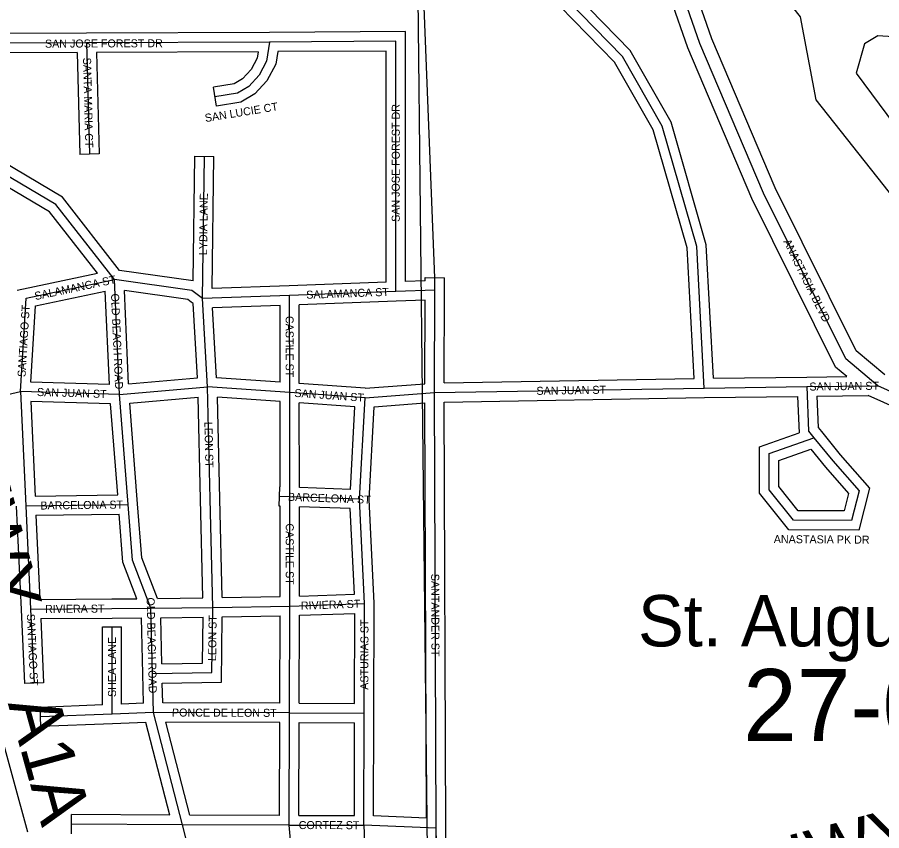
# Model space of a CAD drawing. Extents: x 418523 to 616617, y 1878279 to 2196743.
# Drawn here: x 566933 to 569632, y 2010108 to 2012645 of the extents above; entities that cross this region are included whole.
import ezdxf

# ---------------------------------------------------------------- set-up
doc = ezdxf.new("R2010")
doc.units = 0
for name, color, linetype in [('Level 1', 7, 'Continuous'), ('Level 2', 7, 'Continuous'), ('Level 22', 7, 'Continuous'), ('Level 23', 7, 'Continuous'), ('Level 28', 7, 'Continuous'), ('Level 31', 7, 'Continuous'), ('Level 32', 7, 'Continuous'), ('Level 34', 7, 'Continuous'), ('Level 44', 7, 'Continuous'), ('Level 5', 7, 'Continuous'), ('Level 8', 7, 'Continuous')]:
    doc.layers.add(name, color=color, linetype=linetype)

msp = doc.modelspace()

# ---------------------------------------------------------------- linework, layer by layer
at = {"layer": 'Level 1'}
msp.add_line((568168.027, 2014072.298), (568225.789, 2008858.623), dxfattribs=at)
at = {"layer": 'Level 22'}
for points in [[(569619.639, 2011495.826), (569519.67, 2011579.341), (569262.559, 2012096.71), (569063.974, 2012564.119), (568906.562, 2013014.704), (568898.539, 2013106.366), (568840.396, 2013181.781), (568832.354, 2013265.078)], [(571506.093, 2009348.016), (571532.95, 2009998.175), (571459.084, 2010407.097), (571417.473, 2010507.2), (571093.355, 2010849.789), (570477.21, 2011151.608), (569919.184, 2011361.657), (569619.639, 2011495.826)]]:
    msp.add_lwpolyline(points, dxfattribs=at)
at = {"layer": 'Level 23'}
msp.add_line((566965.801, 2010103.183), (566763.775, 2010837.889), dxfattribs=at)
for points in [[(569641.039, 2011530.071), (569551.756, 2011604.658), (569298.909, 2012113.446), (569101.304, 2012578.551), (568945.974, 2013023.175), (568937.365, 2013121.516), (568879.105, 2013197.086), (568871.6, 2013274.826)], [(569522.769, 2011524.63), (569487.584, 2011554.023), (569226.208, 2012079.973), (569026.644, 2012549.686), (568867.149, 2013006.234), (568859.711, 2013091.215), (568801.688, 2013166.477), (568793.637, 2013249.865)], [(571468.544, 2009408.178), (571492.801, 2009995.411), (571420.488, 2010395.734), (571383.359, 2010485.053), (571069.266, 2010817.047), (570461.33, 2011114.844), (569903.948, 2011324.651), (569589.599, 2011465.451)]]:
    msp.add_lwpolyline(points, dxfattribs=at)
at = {"layer": 'Level 31'}
for p, q in [((567149.488, 2012565.451), (566868.651, 2012564.315)), ((567720.038, 2012568.068), (567149.488, 2012565.451)), ((567149.488, 2012565.451), (567158.155, 2012218.498)), ((567511.125, 2011768.159), (567516.95, 2012211.446)), ((566960.859, 2011769.496), (567236.134, 2011827.376)), ((567251.748, 2011468.769), (567236.134, 2011827.376)), ((568236.428, 2011794.412), (568236.52, 2011832.96)), ((568236.428, 2011794.412), (568114.381, 2011789.614)), ((568235.662, 2011474.395), (568236.428, 2011794.412)), ((566943.35, 2011477.883), (566960.859, 2011769.496)), ((567783.114, 2011777.684), (567511.125, 2011768.159)), ((567526.943, 2011492.831), (567511.125, 2011768.159)), ((568114.381, 2011789.614), (567783.114, 2011777.684)), ((567783.334, 2011474.756), (567783.114, 2011777.684)), ((566618.267, 2011403.763), (566943.35, 2011477.883)), ((567251.748, 2011468.769), (566943.35, 2011477.883)), ((566943.35, 2011477.883), (566959.918, 2011121.456)), ((567251.748, 2011468.769), (567526.943, 2011492.831)), ((567783.334, 2011474.756), (567526.943, 2011492.831)), ((567535.289, 2011142.606), (567526.943, 2011492.831)), ((568018.809, 2011458.187), (567783.334, 2011474.756)), ((567783.502, 2011149.281), (567783.334, 2011474.756)), ((568018.809, 2011458.187), (568235.662, 2011474.395)), ((568235.662, 2011474.395), (569077.589, 2011488.747)), ((568240.331, 2010115.39), (568235.662, 2011474.395)), ((569077.589, 2011488.747), (569397.747, 2011493.079)), ((569397.747, 2011493.079), (569619.639, 2011495.826)), ((567278.81, 2011125.409), (567251.748, 2011468.769)), ((568001.249, 2011141.482), (568018.809, 2011458.187)), ((569280.288, 2011284.254), (569420.193, 2011333.743)), ((567783.502, 2011149.281), (567751.173, 2011150.45)), ((568001.249, 2011141.482), (567783.502, 2011149.281)), ((567783.633, 2010808.531), (567783.502, 2011149.281)), ((566959.918, 2011121.456), (567278.81, 2011125.409)), ((566959.918, 2011121.456), (566974.668, 2010799.22)), ((567543.349, 2010804.385), (567535.289, 2011142.606)), ((568016.952, 2010816.333), (568001.249, 2011141.482)), ((566974.668, 2010799.22), (567228.575, 2010800.783)), ((566974.668, 2010799.22), (566985.199, 2010567.907)), ((567228.575, 2010800.783), (567349.982, 2010801.58)), ((567349.982, 2010801.58), (567543.349, 2010804.385)), ((567354.877, 2010597.556), (567349.982, 2010801.58)), ((567543.349, 2010804.385), (567783.633, 2010808.531)), ((567782.829, 2010475.059), (567783.633, 2010808.531)), ((567783.633, 2010808.531), (568016.952, 2010816.333)), ((568016.131, 2010474.496), (568016.952, 2010816.333)), ((567228.728, 2010471.308), (567228.753, 2010743.326)), ((567357.754, 2010476.451), (567354.877, 2010597.556)), ((567357.754, 2010476.451), (567228.728, 2010471.308)), ((567782.829, 2010475.059), (567357.754, 2010476.451)), ((567448.516, 2010126.026), (567357.754, 2010476.451)), ((567781.671, 2010125.221), (567782.829, 2010475.059)), ((567782.829, 2010475.059), (568016.131, 2010474.496)), ((568015.29, 2010124.659), (568016.131, 2010474.496)), ((567228.728, 2010471.308), (567005.548, 2010462.396)), ((567448.516, 2010126.026), (567102.05, 2010127.595)), ((567781.671, 2010125.221), (567448.516, 2010126.026)), ((567530.823, 2009817.445), (567448.516, 2010126.026)), ((567781.671, 2010125.221), (568015.29, 2010124.659)), ((567798.029, 2009941.534), (567781.671, 2010125.221)), ((568240.331, 2010115.39), (568015.29, 2010124.659)), ((568015.29, 2010124.659), (568024.985, 2009805.343)), ((568247.774, 2009781.897), (568240.331, 2010115.39))]:
    msp.add_line(p, q, dxfattribs=at)
for points in [[(569077.589, 2011488.747), (569053.914, 2011930.649), (568946.4, 2012306.201), (568822.03, 2012523.239), (568431.216, 2012924.561)], [(567720.038, 2012568.068), (567711.019, 2012508.813), (567687.775, 2012464.866), (567655.359, 2012429.67), (567620.443, 2012409.026), (567550.048, 2012397.559)], [(568114.381, 2011789.614), (568114.669, 2012570.39), (567720.038, 2012568.068)], [(567236.134, 2011827.376), (567053.49, 2012061.288), (566805.024, 2012208.085)], [(567511.125, 2011768.159), (567494.039, 2011780.928), (567477.904, 2011793.331), (567236.134, 2011827.376)], [(569397.747, 2011493.079), (569403.442, 2011354.511), (569420.193, 2011333.743)], [(569420.193, 2011333.743), (569479.297, 2011261.235), (569560.858, 2011167.946), (569537.181, 2011074.905), (569355.871, 2011076.061), (569280.019, 2011170.793), (569280.288, 2011284.254)], [(567349.982, 2010801.58), (567292.338, 2010951.911), (567278.81, 2011125.409)], [(567354.877, 2010597.556), (567540.639, 2010600.742), (567543.349, 2010804.385)]]:
    msp.add_lwpolyline(points, dxfattribs=at)
at = {"layer": 'Level 32'}
for p, q in [((567149.366, 2012595.45), (566868.529, 2012594.315)), ((567719.9, 2012598.068), (567149.35, 2012595.45)), ((567120.232, 2012535.33), (566900.094, 2012534.441)), ((567120.231, 2012535.33), (567128.165, 2012217.749)), ((567685.101, 2012537.906), (567180.244, 2012535.59)), ((567180.244, 2012535.59), (567188.147, 2012219.247)), ((567554.87, 2012367.948), (567545.224, 2012427.169)), ((567188.147, 2012219.247), (567128.165, 2012217.749)), ((567481.844, 2011823.073), (567486.953, 2012211.84)), ((567486.953, 2012211.84), (567546.949, 2012211.051)), ((567541.538, 2011799.242), (567546.949, 2012211.051)), ((567481.844, 2011823.073), (567252.321, 2011855.392)), ((566932.284, 2011794.143), (567182.878, 2011846.833)), ((568206.498, 2011823.259), (568144.394, 2011820.818)), ((568206.498, 2011823.26), (568206.52, 2011833.032)), ((568206.52, 2011833.032), (568266.521, 2011832.887)), ((568266.429, 2011794.34), (568266.521, 2011832.887)), ((567782.064, 2011807.666), (567541.538, 2011799.241)), ((568084.391, 2011818.554), (567782.034, 2011807.665)), ((568265.736, 2011504.911), (568266.429, 2011794.341)), ((566989.435, 2011744.846), (567207.701, 2011790.739)), ((567220.373, 2011499.709), (567207.701, 2011790.739)), ((567280.357, 2011501.385), (567267.676, 2011792.636)), ((566975.151, 2011506.956), (566989.435, 2011744.846)), ((567495.323, 2011520.181), (567481.977, 2011752.49)), ((567753.136, 2011746.615), (567542.838, 2011739.251)), ((567753.311, 2011506.946), (567753.136, 2011746.615)), ((567813.315, 2011502.72), (567813.135, 2011748.744)), ((568115.461, 2011759.633), (567813.136, 2011748.745)), ((568206.353, 2011763.205), (568115.559, 2011759.636)), ((568205.729, 2011502.241), (568206.354, 2011763.205)), ((567555.382, 2011520.901), (567542.837, 2011739.25)), ((569397.376, 2011523.077), (569522.769, 2011524.63)), ((567220.373, 2011499.709), (566975.151, 2011506.956)), ((567280.357, 2011501.385), (567495.323, 2011520.181)), ((567753.311, 2011506.946), (567555.382, 2011520.901)), ((568018.744, 2011488.266), (567813.315, 2011502.721)), ((568018.744, 2011488.266), (568205.729, 2011502.241)), ((568265.736, 2011504.911), (569045.967, 2011518.213)), ((569106.005, 2011519.135), (569397.342, 2011523.076)), ((566974.823, 2011446.937), (566988.541, 2011151.813)), ((567223.956, 2011439.576), (566974.824, 2011446.938)), ((567283.994, 2011441.472), (567497.714, 2011460.159)), ((567505.298, 2011141.891), (567497.714, 2011460.159)), ((567753.349, 2011446.794), (567557.721, 2011460.586)), ((567565.282, 2011143.321), (567557.721, 2011460.586)), ((567753.486, 2011180.386), (567753.349, 2011446.794)), ((568265.764, 2011444.901), (569077.995, 2011458.749)), ((568270.331, 2010115.775), (568265.764, 2011444.902)), ((569077.995, 2011458.749), (569368.971, 2011462.686)), ((569368.971, 2011462.686), (569373.639, 2011349.097)), ((569428.992, 2011463.462), (569589.599, 2011465.451)), ((567246.385, 2011155.009), (567223.956, 2011439.576)), ((567308.719, 2011127.766), (567283.994, 2011441.472)), ((567987.219, 2011430.334), (567813.353, 2011442.568)), ((567813.488, 2011178.226), (567813.353, 2011442.568)), ((567972.924, 2011172.516), (567987.219, 2011430.335)), ((568031.29, 2011141.375), (568047.306, 2011430.232)), ((568047.307, 2011430.232), (568205.773, 2011442.076)), ((568210.224, 2010146.655), (568205.774, 2011442.075)), ((569250.338, 2011305.481), (569373.639, 2011349.097)), ((569310.24, 2011263.026), (569410.286, 2011298.415)), ((567750.089, 2011120.468), (567752.257, 2011180.431)), ((567753.486, 2011180.386), (567752.257, 2011180.431)), ((567972.924, 2011172.516), (567813.488, 2011178.226)), ((566988.541, 2011151.813), (567246.385, 2011155.009)), ((566929.949, 2011120.085), (566944.699, 2010797.847)), ((567512.637, 2010833.943), (567505.298, 2011141.892)), ((567572.632, 2010834.894), (567565.282, 2011143.321)), ((567753.513, 2011120.344), (567750.089, 2011120.468)), ((567753.623, 2010838.017), (567753.514, 2011120.344)), ((568046.955, 2010817.021), (568031.291, 2011141.373)), ((566991.307, 2011091.842), (567251.085, 2011095.061)), ((567813.622, 2010839.551), (567813.514, 2011118.186)), ((567972.614, 2011112.487), (567813.515, 2011118.186)), ((567985.518, 2010845.3), (567972.614, 2011112.487)), ((566991.307, 2011091.842), (567003.319, 2010829.396)), ((567003.319, 2010829.396), (567228.39, 2010830.783)), ((567228.379, 2010830.783), (567306.458, 2010831.295)), ((567370.494, 2010831.881), (567512.636, 2010833.943)), ((567572.633, 2010834.894), (567753.622, 2010838.017)), ((567813.623, 2010839.551), (567985.518, 2010845.299)), ((566944.699, 2010797.855), (566955.23, 2010566.542)), ((568046.132, 2010474.424), (568046.955, 2010817.021)), ((567006.057, 2010769.411), (567228.76, 2010770.783)), ((567006.057, 2010769.411), (567015.169, 2010569.271)), ((567228.772, 2010770.783), (567320.698, 2010771.386)), ((567324.885, 2010596.836), (567320.698, 2010771.386)), ((567380.701, 2010772.021), (567512.941, 2010773.939)), ((567384.155, 2010628.061), (567380.701, 2010772.021)), ((567572.96, 2010774.89), (567753.559, 2010778.006)), ((567752.903, 2010505.156), (567753.559, 2010778.006)), ((567812.904, 2010504.986), (567813.564, 2010779.513)), ((567813.564, 2010779.514), (567986.878, 2010785.31)), ((567986.204, 2010504.569), (567986.878, 2010785.31)), ((567198.73, 2010500.134), (567198.753, 2010743.327)), ((567198.753, 2010743.327), (567258.754, 2010743.322)), ((567258.732, 2010502.528), (567258.754, 2010743.322)), ((567327.062, 2010505.251), (567324.885, 2010596.842)), ((567015.169, 2010569.271), (566955.23, 2010566.542)), ((567387.053, 2010506.355), (567385.587, 2010568.076)), ((567198.729, 2010500.135), (567004.35, 2010492.372)), ((567327.061, 2010505.251), (567258.732, 2010502.528)), ((567752.903, 2010505.156), (567387.053, 2010506.354)), ((567812.904, 2010504.986), (567986.203, 2010504.568)), ((567006.745, 2010432.418), (567004.35, 2010492.372)), ((568045.361, 2010153.446), (568046.132, 2010474.424)), ((567334.778, 2010445.509), (567229.923, 2010441.331)), ((567409.71, 2010156.203), (567334.777, 2010445.509)), ((567752.73, 2010445.156), (567396.549, 2010446.321)), ((567471.752, 2010155.97), (567396.549, 2010446.321)), ((567751.77, 2010155.293), (567752.731, 2010445.155)), ((567811.771, 2010155.149), (567812.732, 2010444.985)), ((567812.732, 2010444.985), (567986.059, 2010444.568)), ((567229.925, 2010441.331), (567006.745, 2010432.418)), ((567985.364, 2010154.731), (567986.059, 2010444.568)), ((567101.914, 2010097.594), (567102.186, 2010157.595)), ((567409.711, 2010156.203), (567102.186, 2010157.595)), ((567751.77, 2010155.293), (567471.752, 2010155.97)), ((567811.772, 2010155.148), (567985.364, 2010154.731)), ((568210.223, 2010146.655), (568045.361, 2010153.446)), ((568277.76, 2009782.848), (568270.332, 2010115.775))]:
    msp.add_line(p, q, dxfattribs=at)
for points in [[(569106.005, 2011519.135), (569083.69, 2011935.643), (568974.241, 2012317.958), (568846.172, 2012541.449), (568463.408, 2012934.506)], [(569045.968, 2011518.213), (569024.137, 2011925.655), (568918.56, 2012294.444), (568797.889, 2012505.029), (568413.246, 2012900.013)], [(568144.394, 2011820.818), (568144.681, 2012600.567), (567719.861, 2012598.068)], [(567685.101, 2012537.906), (567682.124, 2012518.35), (567663.074, 2012482.331), (567636.286, 2012453.246), (567610.039, 2012437.727), (567545.224, 2012427.169)], [(567745.842, 2012538.217), (567739.914, 2012499.276), (567712.477, 2012447.401), (567674.433, 2012406.095), (567630.846, 2012380.324), (567554.87, 2012367.948)], [(568084.392, 2011818.553), (568084.658, 2012540.211), (567745.842, 2012538.217)], [(567252.321, 2011855.392), (567073.641, 2012084.228), (566847.485, 2012217.843)], [(567182.878, 2011846.833), (567033.339, 2012038.348), (566789.764, 2012182.256)], [(567481.977, 2011752.49), (567475.917, 2011757.019), (567465.89, 2011764.726), (567267.676, 2011792.636)], [(569428.991, 2011463.462), (569433.011, 2011365.637), (569443.545, 2011352.578)], [(569443.545, 2011352.578), (569502.224, 2011280.591), (569593.819, 2011175.823), (569560.466, 2011044.755), (569341.386, 2011046.152), (569249.994, 2011160.293), (569250.339, 2011305.481)], [(569410.286, 2011298.415), (569456.369, 2011241.878), (569527.896, 2011160.067), (569513.897, 2011105.054), (569370.356, 2011105.971), (569310.044, 2011181.292), (569310.239, 2011263.026)], [(567370.494, 2010831.881), (567321.909, 2010958.585), (567308.72, 2011127.741)], [(567306.458, 2010831.295), (567262.767, 2010945.237), (567251.085, 2011095.062)], [(567384.155, 2010628.061), (567511.028, 2010630.239), (567512.941, 2010773.939)], [(567385.587, 2010568.076), (567570.249, 2010571.245), (567572.96, 2010774.891)]]:
    msp.add_lwpolyline(points, dxfattribs=at)
at = {"layer": 'Level 5'}
for points in [[(569750.749, 2011978.684), (569426.974, 2012388.21), (569377.769, 2012646.805), (569286.464, 2012763.806), (569137.485, 2013097.752), (568914.627, 2013790.386), (568839.954, 2013899.016), (568708.072, 2014366.276), (568533.993, 2014666.941)], [(570019.405, 2012561.381), (569619.365, 2012587.656), (569577.584, 2012562.786), (569552.276, 2012471.183), (569817.869, 2012111.838)]]:
    msp.add_lwpolyline(points, dxfattribs=at)
at = {"layer": 'Level 8'}
msp.add_lwpolyline([(568247.423, 2009781.606), (568240.417, 2010115.614), (568235.393, 2011474.645), (568236.387, 2011794.651), (568236.386, 2011832.652), (568201.369, 2012730.672), (566894.339, 2012719.656), (566882.322, 2013628.677), (566862.314, 2014034.686), (566014.294, 2014023.676), (565950.294, 2014022.675), (565593.285, 2014017.67), (565546.284, 2014017.67), (565543.282, 2014141.672), (565535.275, 2014507.681), (565532.272, 2014673.684)], dxfattribs=at)

# ---------------------------------------------------------------- texts
at = {"layer": 'Level 2'}
msp.add_text('27-07-30', height=225, dxfattribs=at).set_placement((569199.176, 2010386.903))
at = {"layer": 'Level 28'}
for s, rotation, p in [('HWY', 285.374, (566725.3, 2011256.837)), ('A1A', 285.374, (566903.081, 2010505.01)), ('STATE HWY A1A', 14.667769, (568549.158, 2009720.321))]:
    msp.add_text(s, height=160, rotation=rotation, dxfattribs=at).set_placement(p)
at = {"layer": 'Level 34'}
for s, height, rotation, p in [('SAN JOSE FOREST DR', 25, 0.218956, (567019.489, 2012550.606)), ('SANTA MARIA CT', 25, 271.430072, (567138.142, 2012519.181)), ('SAN LUCIE CT', 25, 9.251092, (567520.722, 2012318.357)), ('SAN JOSE FOREST DR', 25, 89.977847, (568126.957, 2012007.085)), ('LYDIA LANE', 25, 89.246106, (567525.399, 2011903.189)), ('ANASTASIA BLVD', 25, 296.424578, (569323.574, 2011945.848)), ('SALAMANCA ST', 25, 11.873406, (566989.644, 2011762.777)), ('SALAMANCA ST', 24.99916, 2.061836, (567835.421, 2011767.063)), ('OLD BEACH ROAD', 25, 272.492125, (567225.557, 2011782.991)), ('SANTIAGO ST', 25, 86.563044, (566958.549, 2011522.492)), ('CASTILE ST', 25, 270.040892, (567770.662, 2011713.613)), ('SAN JUAN ST', 24.99916, 0.708833, (569405.867, 2011480.681)), ('SAN JUAN ST', 25, 358.306511, (566994.233, 2011463.876)), ('SAN JUAN ST', 25, 355.974486, (567797.456, 2011461.232)), ('SAN JUAN ST', 25, 0.975981, (568553.861, 2011467.318)), ('LEON ST', 24.9992, 271.364239, (567517.056, 2011383.067)), ('BARCELONA ST', 25, 357.948297, (567777.669, 2011136.983)), ('BARCELONA ST', 25, 0.709369, (567005.197, 2011109.519)), ('CASTILE ST', 25, 270.020942, (567771.035, 2011066.303)), ('ANASTASIA PK DR', 25, 359.633822, (569294.545, 2011004.911)), ('SANTANDER ST', 25, 270.195861, (568225.104, 2010909.181)), ('OLD BEACH ROAD', 24.99916, 271.373417, (567336.684, 2010834.815)), ('RIVIERA ST', 25, 1.914492, (567818.55, 2010797.195)), ('RIVIERA ST', 25, 0.352342, (567019.494, 2010786.998)), ('SANTIAGO ST', 25, 272.606067, (566962.869, 2010783.521)), ('LEON ST', 25, 89.236417, (567553.616, 2010636.733)), ('ASTURIAS ST', 25, 89.861417, (568028.803, 2010547.117)), ('SHEA LANE', 25, 89.993714, (567241.23, 2010524.638)), ('PONCE DE LEON ST', 25, 359.8117, (567415.763, 2010463.763)), ('CORTEZ ST', 25, 359.861239, (567811.522, 2010112.651))]:
    msp.add_text(s, height=height, rotation=rotation, dxfattribs=at).set_placement(p)
at = {"layer": 'Level 44'}
msp.add_text('St. Augustine', height=160, dxfattribs=at).set_placement((568870.755, 2010682.683))

doc.saveas('drawing.dxf')
